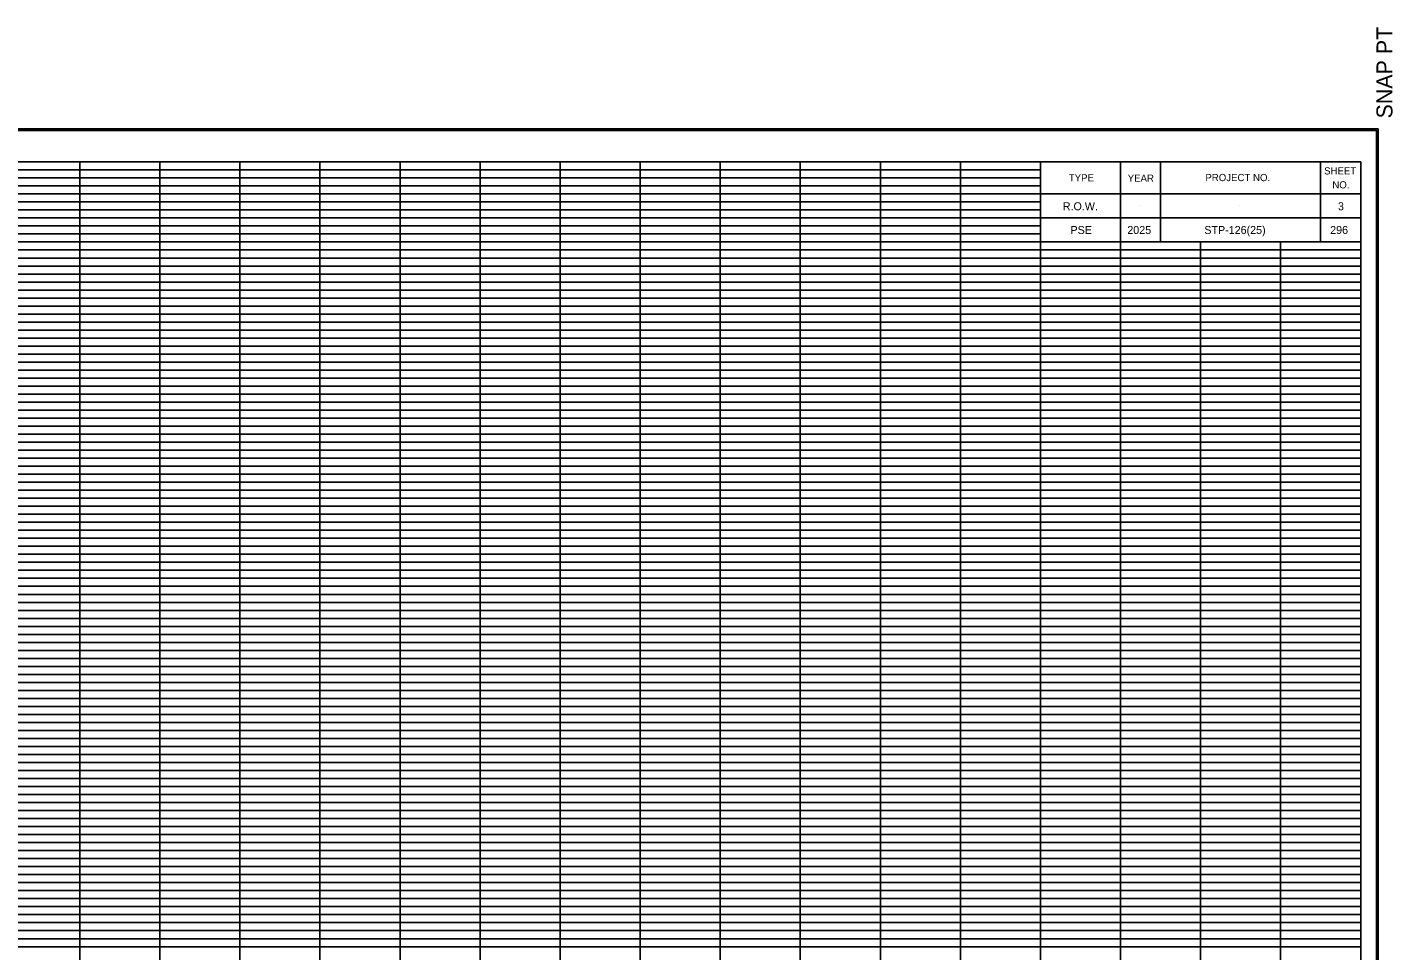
# Model space of a CAD drawing. Extents: x 980 to 2064, y 978 to 2267.
# Drawn here: x 1153.4 to 1324, y 1631.5 to 1746.8 of the extents above; entities that cross this region are included whole.
import ezdxf

# ---------------------------------------------------------------- set-up
doc = ezdxf.new("R2010")
doc.units = 0
for name, color, linetype in [('Default', 7, 'Continuous'), ('DESIGN - SCRATCH - User 1', 7, 'Continuous'), ('DESIGN - SHEET - Corner Text', 7, 'Continuous'), ('DESIGN - SHEET - Light Grid', 7, 'Continuous'), ('DESIGN - SHEET - Linework', 7, 'Continuous'), ('DESIGN - SHEET - Plot Shape', 7, 'Continuous')]:
    doc.layers.add(name, color=color, linetype=linetype)

# ---------------------------------------------------------------- blocks, each defined once
blk = doc.blocks.new('XSTSHT')
at = {"layer": 'DESIGN - SCRATCH - User 1'}
for p, q in [((28.5, 20.45), (28.5, 20.45)), ((29.24, 20.45), (29.24, 20.45)), ((30.49, 20.45), (30.49, 20.45)), ((31.74, 20.45), (31.74, 20.45)), ((28.5, 20.15), (28.5, 20.15)), ((29.24, 20.15), (29.24, 20.15)), ((30.49, 20.15), (30.49, 20.15)), ((31.74, 20.15), (31.74, 20.15))]:
    blk.add_line(p, q, dxfattribs=at)
at = {"layer": 'DESIGN - SHEET - Light Grid'}
for p, q in [((8, 20.9), (16, 20.9)), ((16, 20.9), (24, 20.9)), ((24, 20.9), (28, 20.9)), ((8, 20.8), (16, 20.8)), ((8, 20.7), (16, 20.7)), ((16, 20.8), (24, 20.8)), ((16, 20.7), (24, 20.7)), ((24, 20.8), (28, 20.8)), ((24, 20.7), (28, 20.7)), ((8, 20.6), (16, 20.6)), ((8, 20.5), (16, 20.5)), ((16, 20.6), (24, 20.6)), ((16, 20.5), (24, 20.5)), ((24, 20.6), (28, 20.6)), ((24, 20.5), (28, 20.5)), ((8, 20.4), (16, 20.4)), ((8, 20.3), (16, 20.3)), ((16, 20.4), (24, 20.4)), ((16, 20.3), (24, 20.3)), ((24, 20.4), (28, 20.4)), ((24, 20.3), (28, 20.3)), ((8, 20.2), (16, 20.2)), ((16, 20.2), (24, 20.2)), ((24, 20.2), (28, 20.2)), ((8, 20.1), (16, 20.1)), ((16, 20.1), (24, 20.1)), ((24, 20.1), (28, 20.1)), ((8, 19.9), (16, 19.9)), ((8, 19.8), (16, 19.8)), ((16, 19.9), (24, 19.9)), ((16, 19.8), (24, 19.8)), ((24, 19.9), (32, 19.9)), ((24, 19.8), (32, 19.8)), ((8, 19.7), (16, 19.7)), ((16, 19.7), (24, 19.7)), ((24, 19.7), (32, 19.7)), ((8, 19.6), (16, 19.6)), ((8, 19.5), (16, 19.5)), ((16, 19.6), (24, 19.6)), ((16, 19.5), (24, 19.5)), ((24, 19.6), (32, 19.6)), ((24, 19.5), (32, 19.5)), ((8, 19.4), (16, 19.4)), ((8, 19.3), (16, 19.3)), ((16, 19.4), (24, 19.4)), ((16, 19.3), (24, 19.3)), ((24, 19.4), (32, 19.4)), ((24, 19.3), (32, 19.3)), ((8, 19.2), (16, 19.2)), ((16, 19.2), (24, 19.2)), ((24, 19.2), (32, 19.2)), ((8, 19.1), (16, 19.1)), ((16, 19.1), (24, 19.1)), ((24, 19.1), (32, 19.1)), ((8, 18.9), (16, 18.9)), ((8, 18.8), (16, 18.8)), ((16, 18.9), (24, 18.9)), ((16, 18.8), (24, 18.8)), ((24, 18.9), (32, 18.9)), ((24, 18.8), (32, 18.8)), ((8, 18.7), (16, 18.7)), ((8, 18.6), (16, 18.6)), ((16, 18.7), (24, 18.7)), ((16, 18.6), (24, 18.6)), ((24, 18.7), (32, 18.7)), ((24, 18.6), (32, 18.6)), ((8, 18.5), (16, 18.5)), ((16, 18.5), (24, 18.5)), ((24, 18.5), (32, 18.5)), ((8, 18.4), (16, 18.4)), ((8, 18.3), (16, 18.3)), ((16, 18.4), (24, 18.4)), ((16, 18.3), (24, 18.3)), ((24, 18.4), (32, 18.4)), ((24, 18.3), (32, 18.3)), ((8, 18.2), (16, 18.2)), ((8, 18.1), (16, 18.1)), ((16, 18.2), (24, 18.2)), ((16, 18.1), (24, 18.1)), ((24, 18.2), (32, 18.2)), ((24, 18.1), (32, 18.1)), ((8, 17.9), (16, 17.9)), ((8, 17.8), (16, 17.8)), ((16, 17.9), (24, 17.9)), ((16, 17.8), (24, 17.8)), ((24, 17.9), (32, 17.9)), ((24, 17.8), (32, 17.8)), ((8, 17.7), (16, 17.7)), ((8, 17.6), (16, 17.6)), ((16, 17.7), (24, 17.7)), ((16, 17.6), (24, 17.6)), ((24, 17.7), (32, 17.7)), ((24, 17.6), (32, 17.6)), ((8, 17.5), (16, 17.5)), ((8, 17.4), (16, 17.4)), ((16, 17.5), (24, 17.5)), ((16, 17.4), (24, 17.4)), ((24, 17.5), (32, 17.5)), ((24, 17.4), (32, 17.4)), ((8, 17.3), (16, 17.3)), ((16, 17.3), (24, 17.3)), ((24, 17.3), (32, 17.3)), ((8, 17.2), (16, 17.2)), ((8, 17.1), (16, 17.1)), ((16, 17.2), (24, 17.2)), ((16, 17.1), (24, 17.1)), ((24, 17.2), (32, 17.2)), ((24, 17.1), (32, 17.1)), ((8, 16.9), (16, 16.9)), ((16, 16.9), (24, 16.9)), ((24, 16.9), (32, 16.9)), ((8, 16.8), (16, 16.8)), ((16, 16.8), (24, 16.8)), ((24, 16.8), (32, 16.8)), ((8, 16.7), (16, 16.7)), ((8, 16.6), (16, 16.6)), ((16, 16.7), (24, 16.7)), ((16, 16.6), (24, 16.6)), ((24, 16.7), (32, 16.7)), ((24, 16.6), (32, 16.6)), ((8, 16.5), (16, 16.5)), ((8, 16.4), (16, 16.4)), ((16, 16.5), (24, 16.5)), ((16, 16.4), (24, 16.4)), ((24, 16.5), (32, 16.5)), ((24, 16.4), (32, 16.4)), ((8, 16.3), (16, 16.3)), ((16, 16.3), (24, 16.3)), ((24, 16.3), (32, 16.3)), ((8, 16.2), (16, 16.2)), ((8, 16.1), (16, 16.1)), ((16, 16.2), (24, 16.2)), ((16, 16.1), (24, 16.1)), ((24, 16.2), (32, 16.2)), ((24, 16.1), (32, 16.1)), ((8, 15.9), (16, 15.9)), ((16, 15.9), (24, 15.9)), ((24, 15.9), (32, 15.9)), ((8, 15.8), (16, 15.8)), ((8, 15.7), (16, 15.7)), ((16, 15.8), (24, 15.8)), ((16, 15.7), (24, 15.7)), ((24, 15.8), (32, 15.8)), ((24, 15.7), (32, 15.7)), ((8, 15.6), (16, 15.6)), ((16, 15.6), (24, 15.6)), ((24, 15.6), (32, 15.6)), ((8, 15.5), (16, 15.5)), ((8, 15.4), (16, 15.4)), ((16, 15.5), (24, 15.5)), ((16, 15.4), (24, 15.4)), ((24, 15.5), (32, 15.5)), ((24, 15.4), (32, 15.4)), ((8, 15.3), (16, 15.3)), ((8, 15.2), (16, 15.2)), ((16, 15.3), (24, 15.3)), ((16, 15.2), (24, 15.2)), ((24, 15.3), (32, 15.3)), ((24, 15.2), (32, 15.2)), ((8, 15.1), (16, 15.1)), ((16, 15.1), (24, 15.1)), ((24, 15.1), (32, 15.1)), ((8, 14.9), (16, 14.9)), ((16, 14.9), (24, 14.9)), ((24, 14.9), (32, 14.9)), ((8, 14.8), (16, 14.8)), ((8, 14.7), (16, 14.7)), ((16, 14.8), (24, 14.8)), ((16, 14.7), (24, 14.7)), ((24, 14.8), (32, 14.8)), ((24, 14.7), (32, 14.7)), ((8, 14.6), (16, 14.6)), ((8, 14.5), (16, 14.5)), ((16, 14.6), (24, 14.6)), ((16, 14.5), (24, 14.5)), ((24, 14.6), (32, 14.6)), ((24, 14.5), (32, 14.5)), ((8, 14.4), (16, 14.4)), ((16, 14.4), (24, 14.4)), ((24, 14.4), (32, 14.4)), ((8, 14.3), (16, 14.3)), ((8, 14.2), (16, 14.2)), ((16, 14.3), (24, 14.3)), ((16, 14.2), (24, 14.2)), ((24, 14.3), (32, 14.3)), ((24, 14.2), (32, 14.2)), ((8, 14.1), (16, 14.1)), ((16, 14.1), (24, 14.1)), ((24, 14.1), (32, 14.1)), ((8, 13.9), (16, 13.9)), ((16, 13.9), (24, 13.9)), ((24, 13.9), (32, 13.9)), ((8, 13.8), (16, 13.8)), ((8, 13.7), (16, 13.7)), ((16, 13.8), (24, 13.8)), ((16, 13.7), (24, 13.7)), ((24, 13.8), (32, 13.8)), ((24, 13.7), (32, 13.7)), ((8, 13.6), (16, 13.6)), ((8, 13.5), (16, 13.5)), ((16, 13.6), (24, 13.6)), ((16, 13.5), (24, 13.5)), ((24, 13.6), (32, 13.6)), ((24, 13.5), (32, 13.5)), ((8, 13.4), (16, 13.4)), ((16, 13.4), (24, 13.4)), ((24, 13.4), (32, 13.4)), ((8, 13.3), (16, 13.3)), ((8, 13.2), (16, 13.2)), ((16, 13.3), (24, 13.3)), ((16, 13.2), (24, 13.2)), ((24, 13.3), (32, 13.3)), ((24, 13.2), (32, 13.2)), ((8, 13.1), (16, 13.1)), ((16, 13.1), (24, 13.1)), ((24, 13.1), (32, 13.1)), ((8, 12.9), (16, 12.9)), ((8, 12.8), (16, 12.8)), ((16, 12.9), (24, 12.9)), ((16, 12.8), (24, 12.8)), ((24, 12.9), (32, 12.9)), ((24, 12.8), (32, 12.8)), ((8, 12.7), (16, 12.7)), ((16, 12.7), (24, 12.7)), ((24, 12.7), (32, 12.7)), ((8, 12.6), (16, 12.6)), ((8, 12.5), (16, 12.5)), ((16, 12.6), (24, 12.6)), ((16, 12.5), (24, 12.5)), ((24, 12.6), (32, 12.6)), ((24, 12.5), (32, 12.5)), ((8, 12.4), (16, 12.4)), ((8, 12.3), (16, 12.3)), ((16, 12.4), (24, 12.4)), ((16, 12.3), (24, 12.3)), ((24, 12.4), (32, 12.4)), ((24, 12.3), (32, 12.3)), ((8, 12.2), (16, 12.2)), ((16, 12.2), (24, 12.2)), ((24, 12.2), (32, 12.2)), ((8, 12.1), (16, 12.1)), ((16, 12.1), (24, 12.1)), ((24, 12.1), (32, 12.1)), ((8, 11.9), (16, 11.9)), ((8, 11.8), (16, 11.8)), ((16, 11.9), (24, 11.9)), ((16, 11.8), (24, 11.8)), ((24, 11.9), (32, 11.9)), ((24, 11.8), (32, 11.8)), ((8, 11.7), (16, 11.7)), ((8, 11.6), (16, 11.6)), ((16, 11.7), (24, 11.7)), ((16, 11.6), (24, 11.6)), ((24, 11.7), (32, 11.7)), ((24, 11.6), (32, 11.6)), ((8, 11.5), (16, 11.5)), ((16, 11.5), (24, 11.5)), ((24, 11.5), (32, 11.5)), ((8, 11.4), (16, 11.4)), ((8, 11.3), (16, 11.3)), ((16, 11.4), (24, 11.4)), ((16, 11.3), (24, 11.3)), ((24, 11.4), (32, 11.4)), ((24, 11.3), (32, 11.3)), ((8, 11.2), (16, 11.2)), ((16, 11.2), (24, 11.2)), ((24, 11.2), (32, 11.2))]:
    blk.add_line(p, q, dxfattribs=at)
at = {"layer": 'DESIGN - SHEET - Linework'}
for p, q in [((-1.823, 21.414), (32.217, 21.414)), ((32.217, 21.414), (32.217, -0.414)), ((16, 0), (16, 21)), ((17, 0), (17, 21)), ((18, 0), (18, 21)), ((19, 0), (19, 21)), ((20, 0), (20, 21)), ((21, 0), (21, 21)), ((22, 0), (22, 21)), ((23, 0), (23, 21)), ((24, 0), (24, 21)), ((25, 0), (25, 21)), ((26, 0), (26, 21)), ((27, 0), (27, 21)), ((0, 20), (28, 20)), ((28, 0), (28, 20)), ((29, 0), (29, 20)), ((30, 0), (30, 20)), ((31, 0), (31, 20)), ((0, 19), (32, 19)), ((0, 18), (32, 18)), ((0, 17), (32, 17)), ((0, 16), (32, 16)), ((0, 15), (32, 15)), ((0, 14), (32, 14)), ((0, 13), (32, 13)), ((0, 12), (32, 12))]:
    blk.add_line(p, q, dxfattribs=at)
for points in [[(0, 21), (0, 0), (32, 0), (32, 21), (0, 21)], [(28, 21), (28, 20), (32, 20), (32, 21), (31.5, 21), (31.5, 20), (29.5, 20), (29.5, 21), (29, 21), (29, 20), (32, 20), (28, 20), (28, 20.3), (32, 20.3), (32, 20.6), (28, 20.6)]]:
    blk.add_lwpolyline(points, dxfattribs=at)
at = {"layer": 'DESIGN - SHEET - Plot Shape'}
for points in [[(-1.803, 21.394), (32.197, 21.394), (32.197, -0.394), (-1.803, -0.394)], [(-0.85, 21), (32, 21), (32, -0.25), (-0.85, -0.25)]]:
    blk.add_lwpolyline(points, close=True, dxfattribs=at)
at = {"layer": 'DESIGN - SHEET - Corner Text'}
blk.add_text('  SNAP PT', height=0.2, rotation=90, dxfattribs=at).set_placement((32.397, 21.394))
for s, p in [('TYPE', (28.354, 20.756)), ('YEAR', (29.09, 20.752)), ('PROJECT NO.', (30.06, 20.76)), ('SHEET', (31.543, 20.843)), ('NO.', (31.646, 20.669))]:
    blk.add_text(s, height=0.09, dxfattribs=at).set_placement(p)

msp = doc.modelspace()

# ---------------------------------------------------------------- block references
at = {"layer": 'Default', "xscale": 10, "yscale": 10}
msp.add_blockref('XSTSHT', (1000, 1520), dxfattribs=at)

# ---------------------------------------------------------------- texts
at = {"layer": 'DESIGN - SHEET - Corner Text'}
for s, p in [('R.O.W.', (1282.79, 1723.96)), ('3', (1317.16, 1723.96)), ('PSE', (1283.75, 1721)), ('2025', (1290.85, 1721)), ('STP-126(25)', (1300.47, 1721)), ('296', (1316.19, 1721))]:
    msp.add_text(s, height=1, dxfattribs=at).set_placement(p)

doc.saveas('drawing.dxf')
